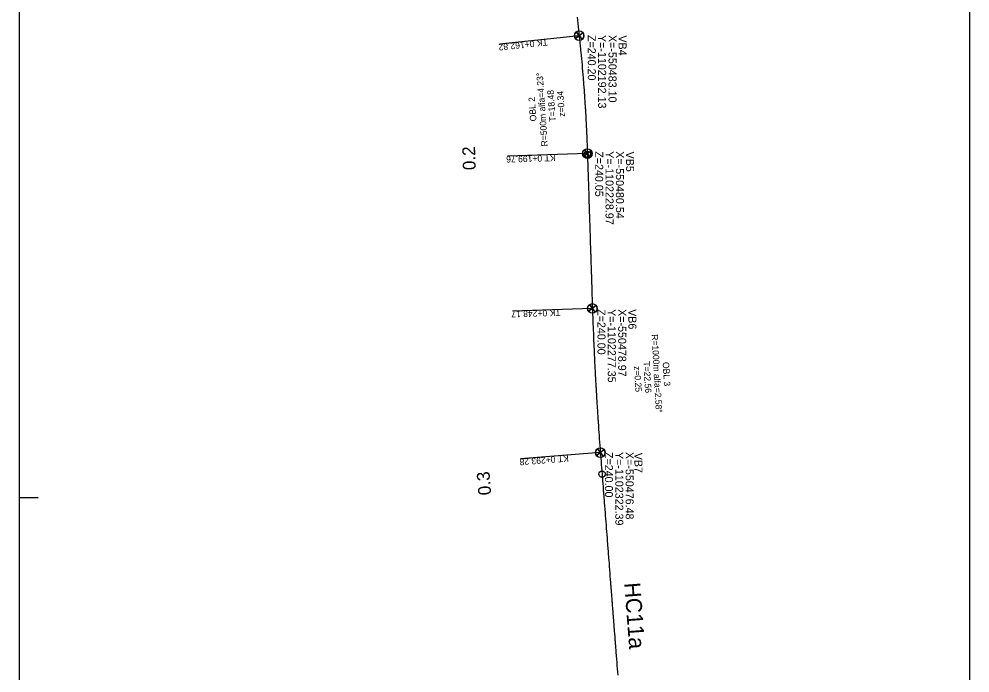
# Model space of a CAD drawing. Extents: x -583517 to -548566, y -1166112 to -1101582.
# Drawn here: x -550658.1 to -550361.1, y -1102391.2 to -1102186.9 of the extents above; entities that cross this region are included whole.
import ezdxf

# ---------------------------------------------------------------- set-up
doc = ezdxf.new("R2010")
doc.units = 0
for name, color, linetype in [('13', 7, 'Continuous'), ('59', 7, 'Continuous'), ('8', 7, 'Continuous'), ('Body pricny rez', 7, 'Continuous'), ('Popis PP', 7, 'Continuous'), ('Rámy', 7, 'Continuous')]:
    doc.layers.add(name, color=color, linetype=linetype)

msp = doc.modelspace()

# ---------------------------------------------------------------- linework, layer by layer
at = {"layer": '13'}
for points in [[(-550483.1, -1102192.13), (-550507.96, -1102194.78)], [(-550480.54, -1102228.97), (-550505.53, -1102229.79)], [(-550478.97, -1102277.35), (-550503.95, -1102278.16)], [(-550476.48, -1102322.39), (-550501.41, -1102324.33)]]:
    msp.add_lwpolyline(points, dxfattribs=at)
at = {"layer": '8'}
for p, q in [((-550481.9, -1102191.23), (-550484.31, -1102193.02)), ((-550484.31, -1102193.02), (-550483.1, -1102192.13)), ((-550484.31, -1102193.02), (-550483.1, -1102192.13)), ((-550484, -1102190.92), (-550482.21, -1102193.33)), ((-550483.1, -1102192.13), (-550484, -1102190.92)), ((-550483.1, -1102192.13), (-550484, -1102190.92)), ((-550481.9, -1102191.23), (-550483.1, -1102192.13)), ((-550483.1, -1102192.13), (-550482.21, -1102193.33)), ((-550481.75, -1102229.87), (-550480.54, -1102228.97)), ((-550481.75, -1102229.87), (-550480.54, -1102228.97)), ((-550479.34, -1102228.08), (-550481.74, -1102229.87)), ((-550481.44, -1102227.77), (-550479.65, -1102230.18)), ((-550480.54, -1102228.97), (-550481.44, -1102227.77)), ((-550480.54, -1102228.97), (-550481.44, -1102227.77)), ((-550479.34, -1102228.08), (-550480.54, -1102228.97)), ((-550480.54, -1102228.97), (-550479.65, -1102230.18)), ((-550477.76, -1102276.45), (-550480.17, -1102278.24)), ((-550478.97, -1102277.35), (-550479.86, -1102276.15)), ((-550479.86, -1102276.15), (-550478.07, -1102278.55)), ((-550478.97, -1102277.35), (-550479.86, -1102276.15)), ((-550477.76, -1102276.45), (-550478.97, -1102277.35)), ((-550480.17, -1102278.24), (-550478.97, -1102277.35)), ((-550480.17, -1102278.24), (-550478.97, -1102277.35)), ((-550478.97, -1102277.35), (-550478.07, -1102278.55)), ((-550477.38, -1102321.19), (-550475.59, -1102323.59)), ((-550476.48, -1102322.39), (-550477.38, -1102321.19)), ((-550476.48, -1102322.39), (-550477.38, -1102321.19)), ((-550475.28, -1102321.5), (-550477.69, -1102323.29)), ((-550477.69, -1102323.29), (-550476.48, -1102322.39)), ((-550477.69, -1102323.29), (-550476.48, -1102322.39)), ((-550475.28, -1102321.5), (-550476.48, -1102322.39)), ((-550476.48, -1102322.39), (-550475.59, -1102323.6))]:
    msp.add_line(p, q, dxfattribs=at)
for centre in [(-550483.1, -1102192.13), (-550480.54, -1102228.97), (-550478.97, -1102277.35), (-550476.48, -1102322.39)]:
    msp.add_circle(centre, 1.5, dxfattribs=at)
for centre, start, end in [((-550483.1, -1102192.13), 126.6271, 216.6271), ((-550483.1, -1102192.13), 126.6271, 216.6271), ((-550483.1, -1102192.13), 306.6271, 36.6271), ((-550480.54, -1102228.97), 126.6271, 216.6271), ((-550480.54, -1102228.97), 126.6271, 216.6271), ((-550480.54, -1102228.97), 306.6271, 36.6271), ((-550478.97, -1102277.35), 126.6271, 216.6271), ((-550478.97, -1102277.35), 126.6271, 216.6271), ((-550478.97, -1102277.35), 306.6271, 36.6271), ((-550476.48, -1102322.39), 126.6271, 216.6271), ((-550476.48, -1102322.39), 126.6271, 216.6271), ((-550476.48, -1102322.39), 306.6271, 36.6271)]:
    msp.add_arc(centre, 1.5, start, end, dxfattribs=at)
at = {"layer": 'Body pricny rez'}
msp.add_lwpolyline([(-550483.72, -1102186.34), (-550483.62, -1102187.33), (-550483.51, -1102188.33), (-550483.4, -1102189.32), (-550483.3, -1102190.32), (-550483.19, -1102191.31), (-550483.1, -1102192.13), (-550483.09, -1102192.31), (-550482.98, -1102193.3), (-550482.88, -1102194.3), (-550482.78, -1102195.29), (-550482.68, -1102196.29), (-550482.64, -1102196.72), (-550482.58, -1102197.28), (-550482.49, -1102198.28), (-550482.39, -1102199.27), (-550482.3, -1102200.27), (-550482.21, -1102201.26), (-550482.21, -1102201.32), (-550482.13, -1102202.26), (-550482.04, -1102203.26), (-550481.96, -1102204.25), (-550481.88, -1102205.25), (-550481.82, -1102205.92), (-550481.81, -1102206.15), (-550481.8, -1102206.25), (-550481.79, -1102206.4), (-550481.78, -1102206.45), (-550481.74, -1102207.04), (-550481.72, -1102207.24), (-550481.65, -1102208.24), (-550481.58, -1102209.11), (-550481.57, -1102209.24), (-550481.51, -1102210.13), (-550481.5, -1102210.24), (-550481.49, -1102210.38), (-550481.48, -1102210.53), (-550481.46, -1102210.82), (-550481.44, -1102211.12), (-550481.43, -1102211.23), (-550481.39, -1102211.86), (-550481.37, -1102212.23), (-550481.34, -1102212.59), (-550481.3, -1102213.23), (-550481.3, -1102213.3), (-550481.29, -1102213.33), (-550481.25, -1102214.07), (-550481.24, -1102214.23), (-550481.2, -1102214.81), (-550481.18, -1102215.13), (-550481.18, -1102215.22), (-550481.16, -1102215.55), (-550481.12, -1102216.22), (-550481.11, -1102216.29), (-550481.07, -1102217.03), (-550481.06, -1102217.22), (-550481.03, -1102217.77), (-550481.01, -1102218.22), (-550480.99, -1102218.5), (-550480.99, -1102218.59), (-550480.95, -1102219.22), (-550480.95, -1102219.24), (-550480.93, -1102219.75), (-550480.91, -1102219.98), (-550480.9, -1102220.22), (-550480.88, -1102220.72), (-550480.85, -1102221.22), (-550480.84, -1102221.46), (-550480.81, -1102222.2), (-550480.81, -1102222.21), (-550480.77, -1102222.94), (-550480.76, -1102223.21), (-550480.74, -1102223.68), (-550480.72, -1102224.21), (-550480.71, -1102224.36), (-550480.71, -1102224.42), (-550480.69, -1102224.92), (-550480.68, -1102225.16), (-550480.68, -1102225.21), (-550480.68, -1102225.27), (-550480.67, -1102225.47), (-550480.65, -1102225.9), (-550480.64, -1102226.21), (-550480.62, -1102226.64), (-550480.6, -1102227.21), (-550480.6, -1102227.38), (-550480.57, -1102228.12), (-550480.57, -1102228.21), (-550480.54, -1102228.86), (-550480.54, -1102228.97), (-550480.53, -1102229.21), (-550480.52, -1102229.59), (-550480.52, -1102229.73), (-550480.51, -1102229.92), (-550480.5, -1102230.21), (-550480.5, -1102230.23), (-550480.5, -1102230.29), (-550480.5, -1102230.33), (-550480.47, -1102231.07), (-550480.47, -1102231.21), (-550480.44, -1102232.21), (-550480.42, -1102232.58), (-550480.4, -1102233.21), (-550480.37, -1102234.21), (-550480.34, -1102235.21), (-550480.31, -1102236.21), (-550480.27, -1102237.21), (-550480.24, -1102238.2), (-550480.21, -1102239.2), (-550480.18, -1102240.2), (-550480.14, -1102241.2), (-550480.12, -1102242.01), (-550480.11, -1102242.2), (-550480.08, -1102243.2), (-550480.05, -1102244.2), (-550480.01, -1102245.2), (-550479.98, -1102246.2), (-550479.95, -1102247.2), (-550479.94, -1102247.52), (-550479.94, -1102247.54), (-550479.92, -1102248.12), (-550479.92, -1102248.14), (-550479.92, -1102248.2), (-550479.88, -1102249.2), (-550479.85, -1102250.2), (-550479.82, -1102251.2), (-550479.79, -1102252.2), (-550479.75, -1102253.2), (-550479.72, -1102254.2), (-550479.69, -1102255.2), (-550479.66, -1102256.2), (-550479.62, -1102257.19), (-550479.59, -1102258.19), (-550479.56, -1102259.19), (-550479.56, -1102259.27), (-550479.54, -1102259.81), (-550479.53, -1102260.13), (-550479.53, -1102260.19), (-550479.51, -1102260.54), (-550479.49, -1102261.19), (-550479.46, -1102262.19), (-550479.43, -1102263.19), (-550479.4, -1102264.19), (-550479.36, -1102265.19), (-550479.33, -1102266.19), (-550479.3, -1102267.19), (-550479.27, -1102268.13), (-550479.27, -1102268.19), (-550479.26, -1102268.24), (-550479.25, -1102268.74), (-550479.24, -1102268.91), (-550479.23, -1102269.19), (-550479.23, -1102269.43), (-550479.22, -1102269.69), (-550479.2, -1102270.19), (-550479.19, -1102270.45), (-550479.17, -1102271.19), (-550479.14, -1102272.19), (-550479.1, -1102273.19), (-550479.07, -1102274.19), (-550479.04, -1102275.19), (-550479.01, -1102276.18), (-550478.97, -1102277.18), (-550478.97, -1102277.35), (-550478.97, -1102277.4), (-550478.94, -1102278.18), (-550478.91, -1102279.18), (-550478.87, -1102280.18), (-550478.84, -1102281.07), (-550478.84, -1102281.18), (-550478.8, -1102282.18), (-550478.76, -1102283.18), (-550478.74, -1102283.79), (-550478.72, -1102284.18), (-550478.68, -1102285.18), (-550478.64, -1102286.18), (-550478.6, -1102287.18), (-550478.58, -1102287.7), (-550478.56, -1102287.99), (-550478.56, -1102288.18), (-550478.55, -1102288.42), (-550478.54, -1102288.55), (-550478.52, -1102289.01), (-550478.51, -1102289.16), (-550478.51, -1102289.18), (-550478.47, -1102290.17), (-550478.47, -1102290.23), (-550478.44, -1102290.77), (-550478.42, -1102291.17), (-550478.38, -1102292.17), (-550478.37, -1102292.32), (-550478.33, -1102293.17), (-550478.28, -1102294.17), (-550478.23, -1102295.17), (-550478.18, -1102296.17), (-550478.15, -1102296.67), (-550478.13, -1102297.17), (-550478.07, -1102298.16), (-550478.02, -1102299.16), (-550477.98, -1102299.84), (-550477.96, -1102300.16), (-550477.93, -1102300.78), (-550477.91, -1102301.12), (-550477.91, -1102301.16), (-550477.87, -1102301.86), (-550477.85, -1102302.16), (-550477.85, -1102302.25), (-550477.83, -1102302.61), (-550477.8, -1102303.1), (-550477.79, -1102303.16), (-550477.78, -1102303.35), (-550477.74, -1102304.09), (-550477.74, -1102304.15), (-550477.7, -1102304.83), (-550477.68, -1102305.15), (-550477.65, -1102305.57), (-550477.61, -1102306.15), (-550477.6, -1102306.32), (-550477.56, -1102307.06), (-550477.55, -1102307.15), (-550477.51, -1102307.8), (-550477.51, -1102307.8), (-550477.49, -1102308.15), (-550477.47, -1102308.54), (-550477.43, -1102309.15), (-550477.42, -1102309.28), (-550477.4, -1102309.53), (-550477.38, -1102309.83), (-550477.38, -1102309.9), (-550477.37, -1102310.03), (-550477.36, -1102310.14), (-550477.35, -1102310.36), (-550477.32, -1102310.77), (-550477.3, -1102311.14), (-550477.28, -1102311.41), (-550477.27, -1102311.51), (-550477.23, -1102312.14), (-550477.22, -1102312.25), (-550477.17, -1102312.99), (-550477.16, -1102313.14), (-550477.12, -1102313.74), (-550477.09, -1102314.13), (-550477.07, -1102314.48), (-550477.02, -1102315.13), (-550477.02, -1102315.22), (-550476.96, -1102315.96), (-550476.96, -1102315.96), (-550476.95, -1102316.13), (-550476.9, -1102316.9), (-550476.88, -1102317.13), (-550476.81, -1102318.12), (-550476.73, -1102319.12), (-550476.66, -1102320.12), (-550476.58, -1102321.12), (-550476.51, -1102322.11), (-550476.48, -1102322.39), (-550476.43, -1102323.11), (-550476.35, -1102324.11), (-550476.27, -1102325.1), (-550476.2, -1102326.1), (-550476.12, -1102327.1), (-550476.04, -1102328.09), (-550475.96, -1102329.09), (-550475.9, -1102329.86), (-550475.89, -1102330.09), (-550475.86, -1102330.38), (-550475.84, -1102330.63), (-550475.84, -1102330.71), (-550475.81, -1102331.09), (-550475.8, -1102331.15), (-550475.79, -1102331.32), (-550475.73, -1102332.08), (-550475.65, -1102333.08), (-550475.58, -1102334.08), (-550475.5, -1102335.07), (-550475.42, -1102336.07), (-550475.38, -1102336.57), (-550475.34, -1102337.07), (-550475.3, -1102337.56), (-550475.27, -1102338.06), (-550475.19, -1102339.06), (-550475.11, -1102340.06), (-550475.11, -1102340.11), (-550475.03, -1102341.06), (-550475.02, -1102341.22), (-550474.96, -1102342.05), (-550474.88, -1102343.05), (-550474.8, -1102344.05), (-550474.72, -1102345.04), (-550474.65, -1102346.04), (-550474.57, -1102347.04), (-550474.49, -1102348.03), (-550474.41, -1102349.03), (-550474.33, -1102350.03), (-550474.27, -1102350.86), (-550474.26, -1102351.03), (-550474.23, -1102351.43), (-550474.22, -1102351.47), (-550474.18, -1102352.02), (-550474.14, -1102352.55), (-550474.1, -1102353.02), (-550474.02, -1102354.02), (-550473.95, -1102355.01), (-550473.91, -1102355.5), (-550473.87, -1102356.01), (-550473.79, -1102357.01), (-550473.71, -1102358), (-550473.64, -1102359), (-550473.56, -1102360), (-550473.48, -1102361), (-550473.4, -1102361.99), (-550473.33, -1102362.99), (-550473.33, -1102363.01), (-550473.27, -1102363.74), (-550473.25, -1102363.99), (-550473.21, -1102364.47), (-550473.17, -1102364.98), (-550473.16, -1102365.19), (-550473.1, -1102365.92), (-550473.09, -1102365.98), (-550473.04, -1102366.65), (-550473.02, -1102366.98), (-550472.99, -1102367.38), (-550472.94, -1102367.97), (-550472.93, -1102368.11), (-550472.91, -1102368.39), (-550472.87, -1102368.84), (-550472.86, -1102368.97), (-550472.85, -1102369.08), (-550472.81, -1102369.57), (-550472.79, -1102369.87), (-550472.78, -1102369.97), (-550472.76, -1102370.3), (-550472.72, -1102370.83), (-550472.71, -1102370.97), (-550472.7, -1102370.99), (-550472.7, -1102371.03), (-550472.66, -1102371.54), (-550472.64, -1102371.76), (-550472.63, -1102371.96), (-550472.59, -1102372.49), (-550472.55, -1102372.96), (-550472.53, -1102373.22), (-550472.47, -1102373.95), (-550472.47, -1102373.96), (-550472.42, -1102374.68), (-550472.4, -1102374.95), (-550472.36, -1102375.41), (-550472.32, -1102375.95), (-550472.3, -1102376.14), (-550472.25, -1102376.87), (-550472.24, -1102376.95), (-550472.19, -1102377.6), (-550472.16, -1102377.94), (-550472.13, -1102378.32), (-550472.09, -1102378.94), (-550472.08, -1102379.05), (-550472.02, -1102379.78), (-550472.01, -1102379.94), (-550471.96, -1102380.51), (-550471.95, -1102380.64), (-550471.93, -1102380.93), (-550471.91, -1102381.24), (-550471.89, -1102381.41), (-550471.85, -1102381.93), (-550471.85, -1102381.97), (-550471.79, -1102382.7), (-550471.78, -1102382.93), (-550471.74, -1102383.43), (-550471.7, -1102383.93), (-550471.68, -1102384.16), (-550471.62, -1102384.89), (-550471.62, -1102384.92), (-550471.57, -1102385.62), (-550471.54, -1102385.92), (-550471.47, -1102386.92), (-550471.39, -1102387.91), (-550471.31, -1102388.91), (-550471.23, -1102389.91), (-550471.16, -1102390.9), (-550471.08, -1102391.9)], dxfattribs=at)
for centre in [(-550480.53, -1102229.21), (-550475.96, -1102329.09)]:
    msp.add_circle(centre, 1, dxfattribs=at)
at = {"layer": 'Popis PP'}
msp.add_line((-550658.05, -1102336.4), (-550652.05, -1102336.4), dxfattribs=at)
at = {"layer": 'Rámy'}
msp.add_lwpolyline([(-550658.05, -1102021.4), (-550658.05, -1102756.4), (-550361.05, -1102756.4), (-550361.05, -1102021.4)], close=True, dxfattribs=at)

# ---------------------------------------------------------------- texts
at = {"layer": '13'}
for s, height, rotation, p in [('TK 0+162.82', 2, 186.0965, (-550493.05, -1102193.19)), ('R=500m alfa=4.23%%d', 2, 93.9797, (-550492.89, -1102226.66)), ('OBL 2', 2, 93.9797, (-550496.44, -1102218.82)), ('  T=18.48', 2, 93.9797, (-550490.32, -1102220.39)), ('   z=0.34', 2, 93.9797, (-550487.37, -1102219.63)), ('0.2', 4, 91.8628, (-550515.39, -1102234.08)), ('KT 0+199.76', 2, 181.8628, (-550490.54, -1102229.3)), ('TK 0+248.17', 2, 181.8628, (-550488.96, -1102277.67)), ('R=1000m alfa=2.58%%d', 2, 273.1552, (-550460.5, -1102285.46)), ('  T=22.56', 2, 273.1552, (-550463.12, -1102292.47)), ('OBL 3', 2, 273.1552, (-550457.02, -1102294.12)), ('   z=0.25', 2, 273.1552, (-550466.09, -1102293.18)), ('KT 0+293.28', 2, 184.4476, (-550486.45, -1102323.17)), ('0.3', 4, 94.4476, (-550510.57, -1102335.55)), ('HC11a', 5, 274.3164, (-550469.03, -1102363.13))]:
    msp.add_text(s, height=height, rotation=rotation, dxfattribs=at).set_placement(p)
at = {"layer": '59'}
for s, p in [('Z=240.20', (-550480.41, -1102191.91)), ('Y=-1102192.13', (-550477.18, -1102191.91)), ('X=-550483.10', (-550473.94, -1102191.91)), ('VB4', (-550470.8, -1102192.04)), ('Z=240.05', (-550478.11, -1102228.23)), ('Y=-1102228.97', (-550474.87, -1102228.23)), ('X=-550480.54', (-550471.63, -1102228.23)), ('VB5', (-550468.47, -1102228.34)), ('Z=240.00', (-550477.39, -1102277.56)), ('Y=-1102277.35', (-550474.16, -1102277.56)), ('X=-550478.97', (-550470.92, -1102277.56)), ('VB6', (-550467.73, -1102277.56)), ('Z=240.00', (-550475.06, -1102322.18)), ('Y=-1102322.39', (-550471.82, -1102322.18)), ('X=-550476.48', (-550468.59, -1102322.18)), ('VB7', (-550465.83, -1102322.42))]:
    msp.add_text(s, height=2.5, rotation=270, dxfattribs=at).set_placement(p)

doc.saveas('drawing.dxf')
